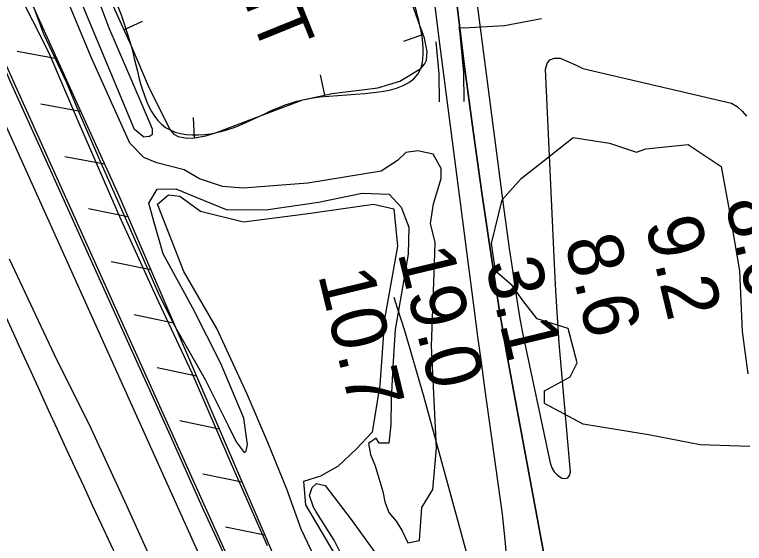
# Model space of a CAD drawing. Extents: x 3598634 to 3636690, y 517270 to 542944.
# Drawn here: x 3631009 to 3631893, y 525018 to 525659 of the extents above; entities that cross this region are included whole.
import ezdxf

# ---------------------------------------------------------------- set-up
doc = ezdxf.new("R2010")
doc.units = 0
for name, color, linetype in [('V-BORW-IDEN', 7, 'Continuous'), ('V-BORW-LINE', 7, 'Continuous'), ('V-FLOD-BASE', 7, 'Continuous'), ('V-LEVE-TOET', 7, 'Continuous'), ('V-RIVR-RANG', 7, 'Continuous'), ('V-ROAD-CNTR', 7, 'Continuous'), ('V-RRAP-FSHR', 7, 'Continuous'), ('V-SITE-VEGE', 7, 'Continuous'), ('V-SURV-LINE', 7, 'Continuous'), ('V-TOPO-DPTH', 7, 'Continuous'), ('V-TOPO-MINR', 7, 'Continuous'), ('V-TOPO-SHOR', 7, 'Continuous')]:
    doc.layers.add(name, color=color, linetype=linetype)

msp = doc.modelspace()

# ---------------------------------------------------------------- linework, layer by layer
at = {"layer": 'V-BORW-LINE'}
for p, q in [((3631141.13, 525640.59), (3631163.9, 525650.9)), ((3631503.92, 525634.87), (3631480.33, 525626.61)), ((3631384.63, 525561.43), (3631379.45, 525585.89)), ((3631226.73, 525509.55), (3631225.51, 525534.52))]:
    msp.add_line(p, q, dxfattribs=at)
msp.add_lwpolyline([(3631109.47, 525710.46), (3631149.85, 525621.36), (3631171.89, 525570.03), (3631197.17, 525519.24), (3631201.67, 525514.05), (3631206.79, 525511.14), (3631217.66, 525509.11), (3631226.77, 525509.55), (3631240.68, 525512.27), (3631253.29, 525516.04), (3631305.71, 525535.82), (3631358.08, 525555.81), (3631393.81, 525563.37), (3631448.93, 525570.23), (3631475.7, 525578.32), (3631501, 525593.63), (3631505.6, 525598.81), (3631507.91, 525604.01), (3631508.87, 525614.18), (3631505.44, 525630.55), (3631500.03, 525646), (3631485.51, 525687.59)], dxfattribs=at)
msp.add_spline([(3630975, 526585.13), (3631052.04, 526605.21), (3631102.86, 526609.48), (3631126.65, 526580.92), (3631214.41, 526427.16), (3631278, 526221.53), (3631364.13, 526008.12), (3631414.49, 525862.79), (3631469.93, 525728.9), (3631500.03, 525646), (3631501, 525593.63), (3631358.08, 525555.81), (3631253.29, 525516.04), (3631197.17, 525519.24), (3631149.85, 525621.36), (3631070.26, 525800.07), (3631011.27, 525958.96), (3630940.05, 526137.74), (3630858.48, 526350.54), (3630820.74, 526446.14), (3630877.89, 526518.85), (3630941.98, 526565.49), (3630975, 526585.13)], degree=3, dxfattribs=at)
at = {"layer": 'V-FLOD-BASE'}
msp.add_lwpolyline([(3631463.55, 524559.65), (3631438.77, 524613.73), (3631409.57, 524679.53), (3631358.71, 524787.06), (3631321.94, 524874.99), (3631280.66, 524966.86), (3631238.08, 525058.09), (3631192.37, 525160.38), (3631149.17, 525255.51), (3631104.09, 525355.84), (3631048.83, 525477.68), (3631003.74, 525577.37), (3630960.59, 525677.04), (3630905.29, 525794.34), (3630863.44, 525894), (3630825.31, 525976.11), (3630783.44, 526073.17), (3630744.16, 526170.2), (3630701.01, 526269.88), (3630664.85, 526353.91), (3630633.73, 526422.97)], dxfattribs=at)
at = {"layer": 'V-LEVE-TOET'}
for points in [[(3630975.12, 525770.97), (3631010.68, 525691.48), (3631050.13, 525612.6), (3631086.92, 525526.62), (3631135.79, 525414.57), (3631182.8, 525311.62), (3631223.48, 525224.95), (3631271.06, 525114.86), (3631314.86, 525015.83)], [(3631190.45, 524963.19), (3631142.81, 525068.09), (3631101.51, 525157.36), (3631056.97, 525246.67), (3631002.3, 525362.67)]]:
    msp.add_lwpolyline(points, dxfattribs=at)
at = {"layer": 'V-ROAD-CNTR'}
for points in [[(3631647.36, 525653.85), (3631602.72, 525645.6), (3631553.49, 525642.68), (3631548.22, 525643.04)], [(3631547.27, 525643.35), (3631548.14, 525639.9), (3631553.03, 525588.76), (3631553.35, 525553.73)], [(3631519.32, 525626.14), (3631523.04, 525587.19), (3631523.35, 525553.45)]]:
    msp.add_lwpolyline(points, dxfattribs=at)
msp.add_arc((3652591.86, 535068.69), 23703.51, 203.728089, 205.708892, dxfattribs=at)
at = {"layer": 'V-RRAP-FSHR'}
for p, q in [((3631059.7, 525605.31), (3631011.7, 525614.28)), ((3631088.63, 525541.57), (3631040.63, 525550.54)), ((3631117.57, 525477.83), (3631069.57, 525486.8)), ((3631146.06, 525413.89), (3631098.24, 525423.79)), ((3631173.75, 525349.61), (3631125.94, 525359.5)), ((3631201.45, 525285.32), (3631153.63, 525295.21)), ((3631229.14, 525221.03), (3631181.32, 525230.93)), ((3631256.83, 525156.74), (3631209.01, 525166.64)), ((3631284.52, 525092.45), (3631236.71, 525102.35)), ((3631312.22, 525028.16), (3631264.4, 525038.06))]:
    msp.add_line(p, q, dxfattribs=at)
msp.add_lwpolyline([(3630676.15, 526428.36), (3630706.37, 526394.05), (3630770.42, 526253.78), (3630975.36, 525791.07), (3631136.09, 525437.05), (3631437.88, 524736.43), (3631513.49, 524581.03), (3631536.52, 524547.17)], dxfattribs=at)
at = {"layer": 'V-SITE-VEGE'}
for points in [[(3630986.11, 525984.89), (3631037.98, 525889.57), (3631056.5, 525842.39), (3631090.07, 525730.75), (3631123.05, 525643.03), (3631163.39, 525549.47), (3631175.48, 525520.49), (3631175.42, 525513.89), (3631174.59, 525513.08), (3631172.1, 525511.45), (3631171.27, 525511.46), (3631165.5, 525510.69), (3631154.04, 525519.87), (3631087.93, 525678.82), (3631056.57, 525763.23), (3631027.71, 525849.26), (3631009.18, 525895.61), (3630988.08, 525931.27)], [(3631900.14, 525135.53), (3631839.81, 525137.74), (3631777.14, 525149.76), (3631698.17, 525162.76), (3631651.11, 525187.68), (3631651.26, 525203.17), (3631682.41, 525219.99), (3631690.73, 525237.04), (3631679.72, 525278.73), (3631642.32, 525290.52), (3631626.21, 525311.06), (3631611.72, 525330.77), (3631591.5, 525348.09), (3631586.93, 525381.57), (3631599.68, 525434.45), (3631622.76, 525460.32), (3631654.81, 525485.29), (3631686.04, 525510.27), (3631730, 525503.32), (3631762.52, 525492.4), (3631773.97, 525496.37), (3631825.4, 525501.58), (3631865.1, 525475.1), (3631875.19, 525422), (3631887.52, 525348.49), (3631890.89, 525275.06), (3631897.73, 525223.62)], [(3631376.85, 524992.17), (3631356.06, 525035.59), (3631338.59, 525083.88), (3631315.49, 525140.37), (3631290.78, 525199.32), (3631254.04, 525278.78), (3631213.93, 525347.67), (3631182.11, 525429.52), (3631195.26, 525440.81), (3631209.11, 525439.05), (3631234.21, 525420.86), (3631286.28, 525408.13), (3631364.66, 525417.97), (3631443.87, 525429.44), (3631468.28, 525423.49), (3631472.74, 525378.6), (3631457.2, 525289.86), (3631451.54, 525210), (3631442.01, 525153.01), (3631423.06, 525132.8), (3631400.84, 525111.82), (3631379.52, 525099.79), (3631359.07, 525093.46), (3631361.24, 525064.9), (3631407.78, 524986.17)]]:
    msp.add_lwpolyline(points, dxfattribs=at)
at = {"layer": 'V-SURV-LINE'}
for points in [[(3630844.13, 525939.44), (3631853.48, 523700.11)], [(3631826.13, 523687.79), (3630816.78, 525927.12)]]:
    msp.add_lwpolyline(points, dxfattribs=at)
at = {"layer": 'V-TOPO-DPTH'}
msp.add_lwpolyline([(3631856.87, 523871.28), (3631785.89, 524273.44), (3631780.14, 524305.74), (3631774.32, 524338.03), (3631768.39, 524370.29), (3631762.4, 524402.55), (3631756.36, 524434.8), (3631750.34, 524467.05), (3631744.33, 524499.3), (3631738.34, 524531.55), (3631606, 525245.29), (3631603.19, 525260.92), (3631600.48, 525276.56), (3631597.94, 525292.23), (3631595.5, 525307.91), (3631576.05, 525437.57), (3631564.52, 525518.17), (3631553.7, 525598.86), (3631543.97, 525679.68), (3631534.96, 525760.6), (3631501.42, 526081.52), (3631500.08, 526094.37), (3631587.57, 526105.55), (3631589.86, 526097.41)], dxfattribs=at)
at = {"layer": 'V-TOPO-MINR'}
for points in [[(3631488.1, 526234.17), (3631491.65, 526181.86), (3631492.37, 526172.1), (3631493.15, 526162.35), (3631494.04, 526152.61), (3631495.01, 526142.87), (3631534.96, 525760.6), (3631543.97, 525679.68), (3631553.7, 525598.86), (3631564.52, 525518.17), (3631576.05, 525437.57), (3631595.5, 525307.91), (3631597.94, 525292.23), (3631600.48, 525276.56), (3631603.19, 525260.92), (3631606, 525245.29), (3631738.34, 524531.55)], [(3631458.16, 526216.71), (3631459.28, 526207.65), (3631462.38, 526181.66), (3631465.37, 526155.66), (3631468.16, 526129.64), (3631470.83, 526103.61), (3631483.11, 525979.2), (3631492.23, 525891), (3631501.89, 525802.87), (3631512.37, 525714.82), (3631523.39, 525626.84), (3631561.75, 525331.58), (3631565.85, 525300.35), (3631570, 525269.13), (3631574.22, 525237.93), (3631578.51, 525206.73), (3631599.69, 525053.73), (3631603.54, 525018.59), (3631606.06, 524983.39)], [(3631506.16, 526158.46), (3631601.86, 525422.79), (3631605.01, 525399.28), (3631608.28, 525375.78), (3631611.73, 525352.31), (3631615.29, 525328.85), (3631621.27, 525290.57), (3631621.97, 525286.27), (3631622.72, 525281.99), (3631623.54, 525277.72), (3631624.41, 525273.46), (3631657.85, 525115.79), (3631659.94, 525110.06), (3631662.85, 525104.97), (3631667.03, 525100.85), (3631672.05, 525097.37), (3631676.1, 525097), (3631679.32, 525097.84), (3631681.29, 525100.52), (3631682.45, 525104.42), (3631671.62, 525228.84), (3631669.05, 525260.72), (3631666.73, 525292.61), (3631664.81, 525324.52), (3631663.15, 525356.46), (3631652.29, 525593.07), (3631654.31, 525599.68), (3631657.72, 525604.38), (3631663.23, 525606.2), (3631670.15, 525606.11), (3631679.42, 525602.38), (3631688.53, 525598.33), (3631697.4, 525593.79), (3631877.8, 525551.88), (3631884.71, 525547.64), (3631890.78, 525542.04), (3631896.14, 525535.93)], [(3631583.33, 524910.34), (3631504.65, 525196.72), (3631497.21, 525223.15), (3631489.56, 525249.51), (3631481.58, 525275.78), (3631473.39, 525301.98), (3631468.89, 525316.08)]]:
    msp.add_lwpolyline(points, dxfattribs=at)
at = {"layer": 'V-TOPO-SHOR'}
for points in [[(3631457.51, 525068.86), (3631462.27, 525055.77), (3631471.14, 525045.08), (3631478.37, 525033.6), (3631485.56, 525018.85), (3631499.46, 525021.98), (3631502.29, 525061.91), (3631515.55, 525083.79), (3631520.11, 525133.49), (3631513.97, 525257.51), (3631517.27, 525345.55), (3631518.45, 525383.05), (3631512.96, 525405.93), (3631516.45, 525429.55), (3631525.72, 525460.45), (3631525.84, 525472.68), (3631516.22, 525489.89), (3631497.5, 525494.15), (3631482.8, 525491.85), (3631472.92, 525482.16), (3631453.23, 525469.3), (3631364.2, 525454.67), (3631285.86, 525448.91), (3631260.6, 525450.78), (3631232.96, 525460.02), (3631214.31, 525470.8), (3631180.96, 525479.28), (3631165.53, 525485.95), (3631148.57, 525503.24), (3631101.46, 525607.26), (3631044.09, 525745.63)], [(3631030.33, 525671.56), (3631043.84, 525635.54), (3631071, 525577.38), (3631085.36, 525543.81), (3631114.87, 525475.84), (3631145.99, 525405.41), (3631182.7, 525321.87), (3631201.89, 525283.36), (3631239.58, 525216.94), (3631267.58, 525161.22), (3631277.17, 525141.55), (3631286.83, 525128.41), (3631289.3, 525130.02), (3631291, 525138.16), (3631286.42, 525170.01), (3631258.52, 525236.33), (3631224.92, 525303.52), (3631188.86, 525369.11), (3631177.02, 525410), (3631171.51, 525430.44), (3631181.46, 525447.47), (3631204.3, 525448.06), (3631229.48, 525437.22), (3631265.22, 525423.01), (3631313.33, 525422.54), (3631377.03, 525431.71), (3631430.14, 525442.61), (3631462.75, 525441.48), (3631477.27, 525425.85), (3631486.82, 525401.29), (3631485.69, 525368.69), (3631477.89, 525321.46), (3631470.13, 525277.5), (3631467.25, 525232.68), (3631465.23, 525192.74)], [(3631465.23, 525192.74), (3631464.93, 525161.76), (3631462.27, 525139.76), (3631450.85, 525139.88), (3631446.83, 525145.62), (3631437.8, 525139.19), (3631440.12, 525126.11)], [(3631440.12, 525126.11), (3631445.69, 525112.2), (3631450.44, 525097.47), (3631455.18, 525081.12), (3631457.51, 525068.86)], [(3631371, 525062.36), (3631366.25, 525076.27), (3631369.6, 525086.03), (3631374.54, 525090.87), (3631385.12, 525088.32), (3631416.52, 525047.24), (3631488.95, 524947.05)], [(3631419.1, 524976.27), (3631395.9, 525022.16), (3631374.21, 525056.62), (3631371, 525062.36)]]:
    msp.add_lwpolyline(points, dxfattribs=at)

# ---------------------------------------------------------------- texts
at = {"layer": 'V-BORW-IDEN'}
msp.add_text('BORROW PIT', height=64, rotation=291.98557, dxfattribs=at).set_placement((3631107.57, 526118.15))
at = {"layer": 'V-RIVR-RANG'}
for s, p in [('8.6', (3631869.49, 525432.09)), ('9.2', (3631772.77, 525406.62)), ('8.6', (3631675.18, 525384.73)), ('19.0', (3631472.83, 525370.71)), ('3.1', (3631579.02, 525356.95)), ('10.7', (3631376.35, 525344.21))]:
    msp.add_text(s, height=67, rotation=283.55833, dxfattribs=at).set_placement(p)

doc.saveas('drawing.dxf')
